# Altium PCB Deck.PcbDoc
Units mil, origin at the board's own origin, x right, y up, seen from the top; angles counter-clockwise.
Board outline 1157.48 x 1190.94 mil, 2 copper layers (Top Layer, Bottom Layer), stack 5.63 mil thick; 39 components, 27 nets, 140 pads, 61 vias.
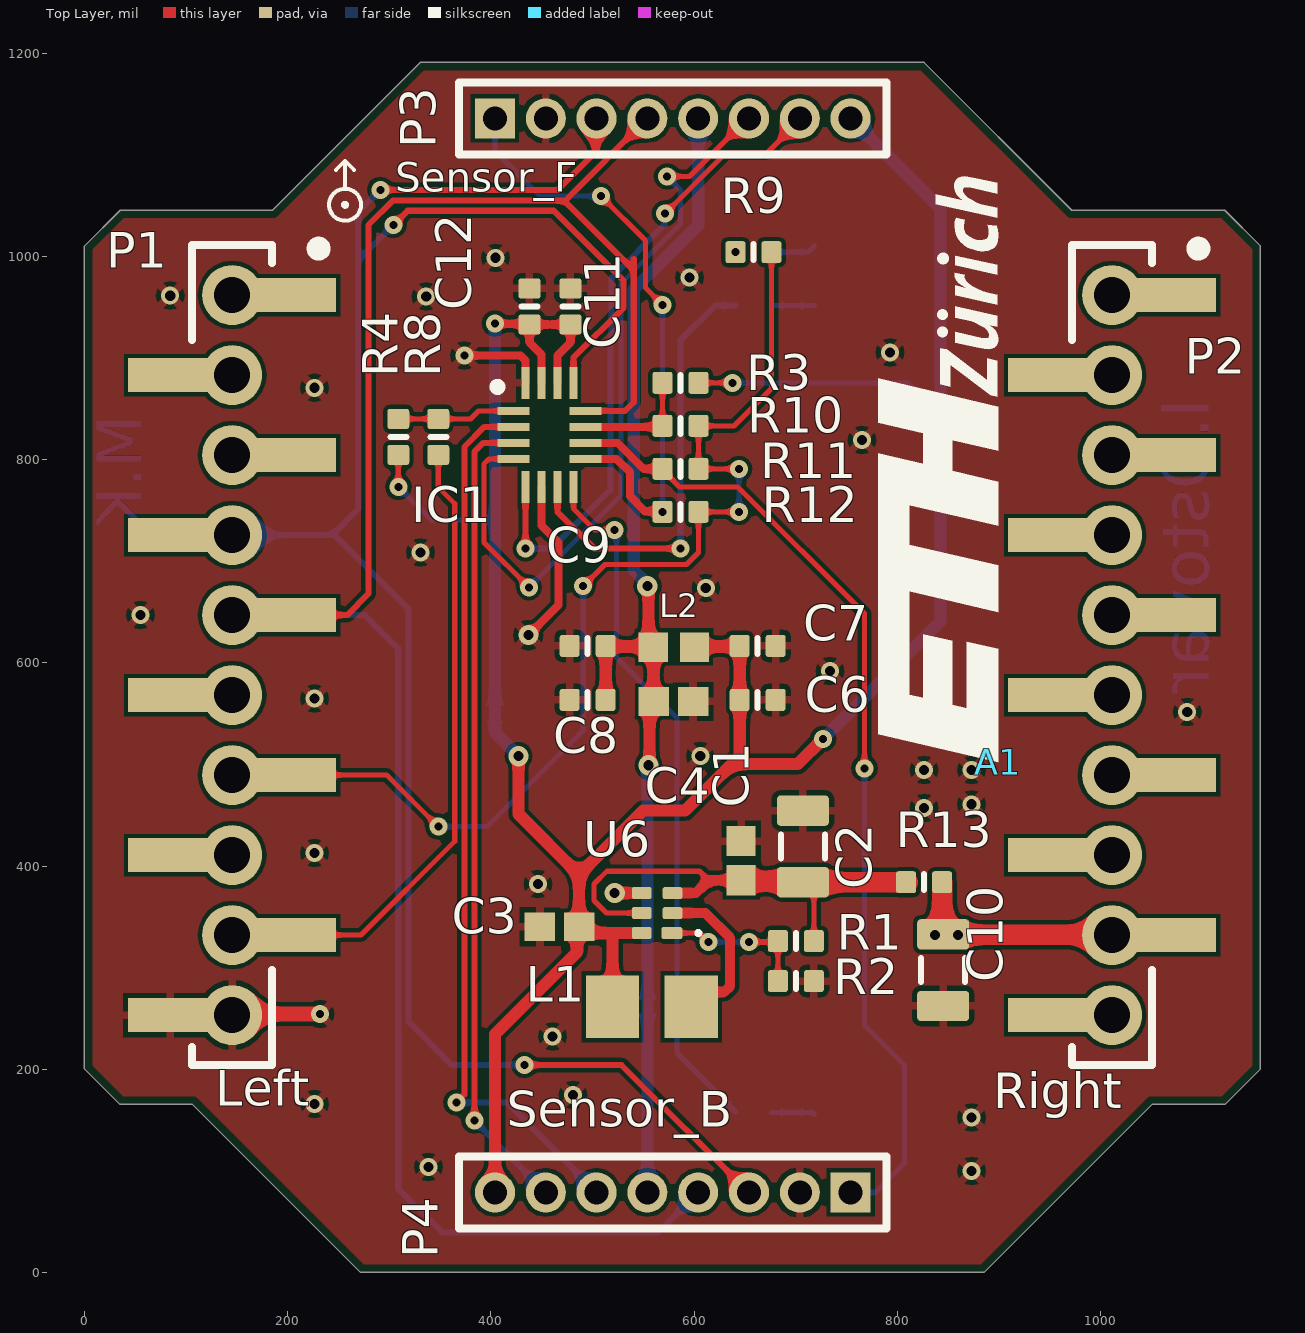
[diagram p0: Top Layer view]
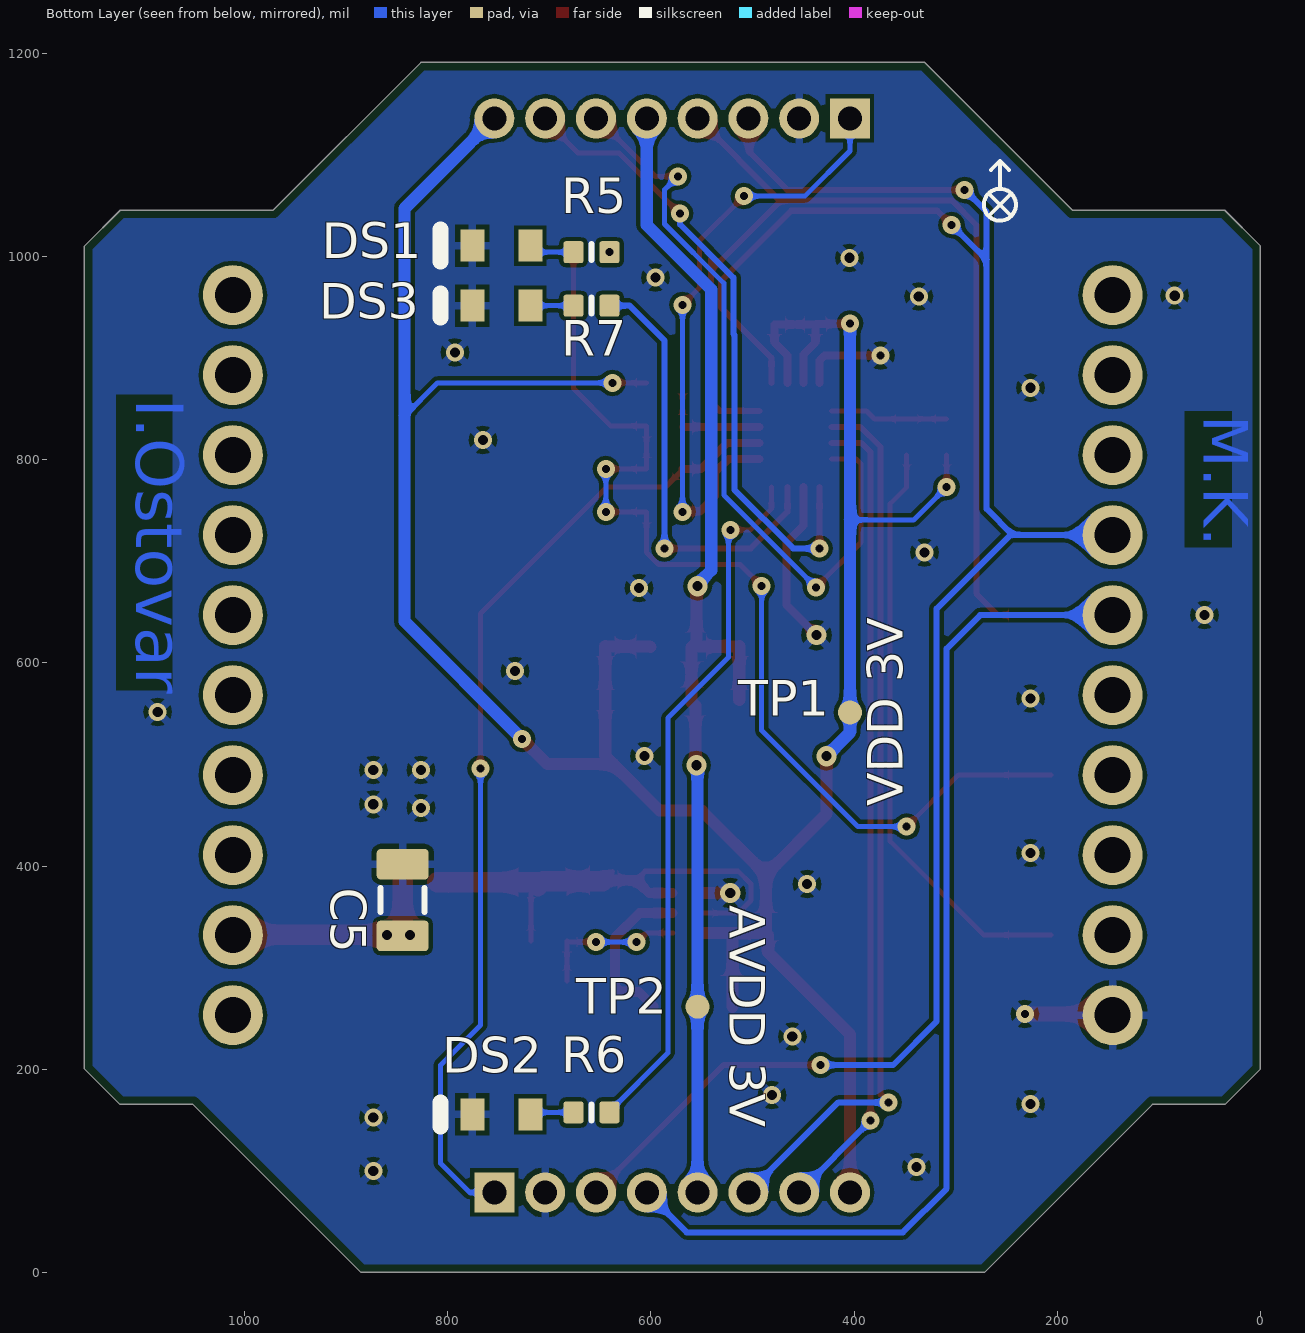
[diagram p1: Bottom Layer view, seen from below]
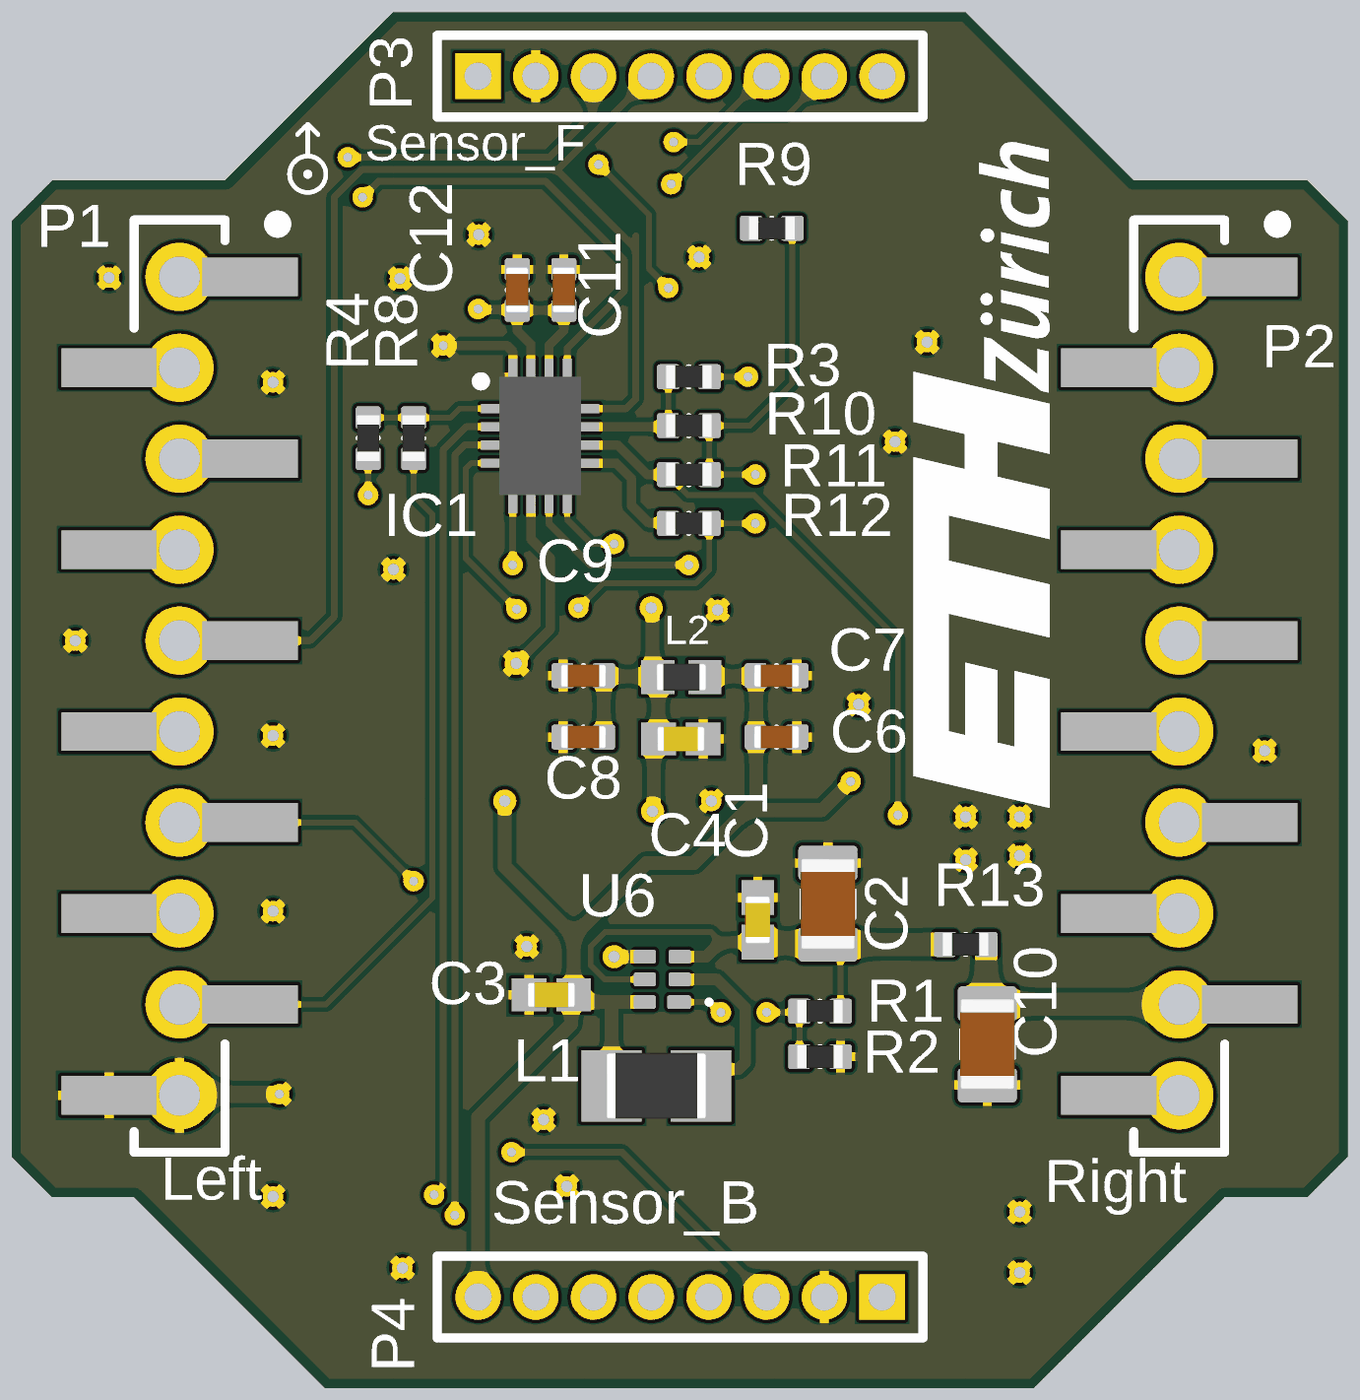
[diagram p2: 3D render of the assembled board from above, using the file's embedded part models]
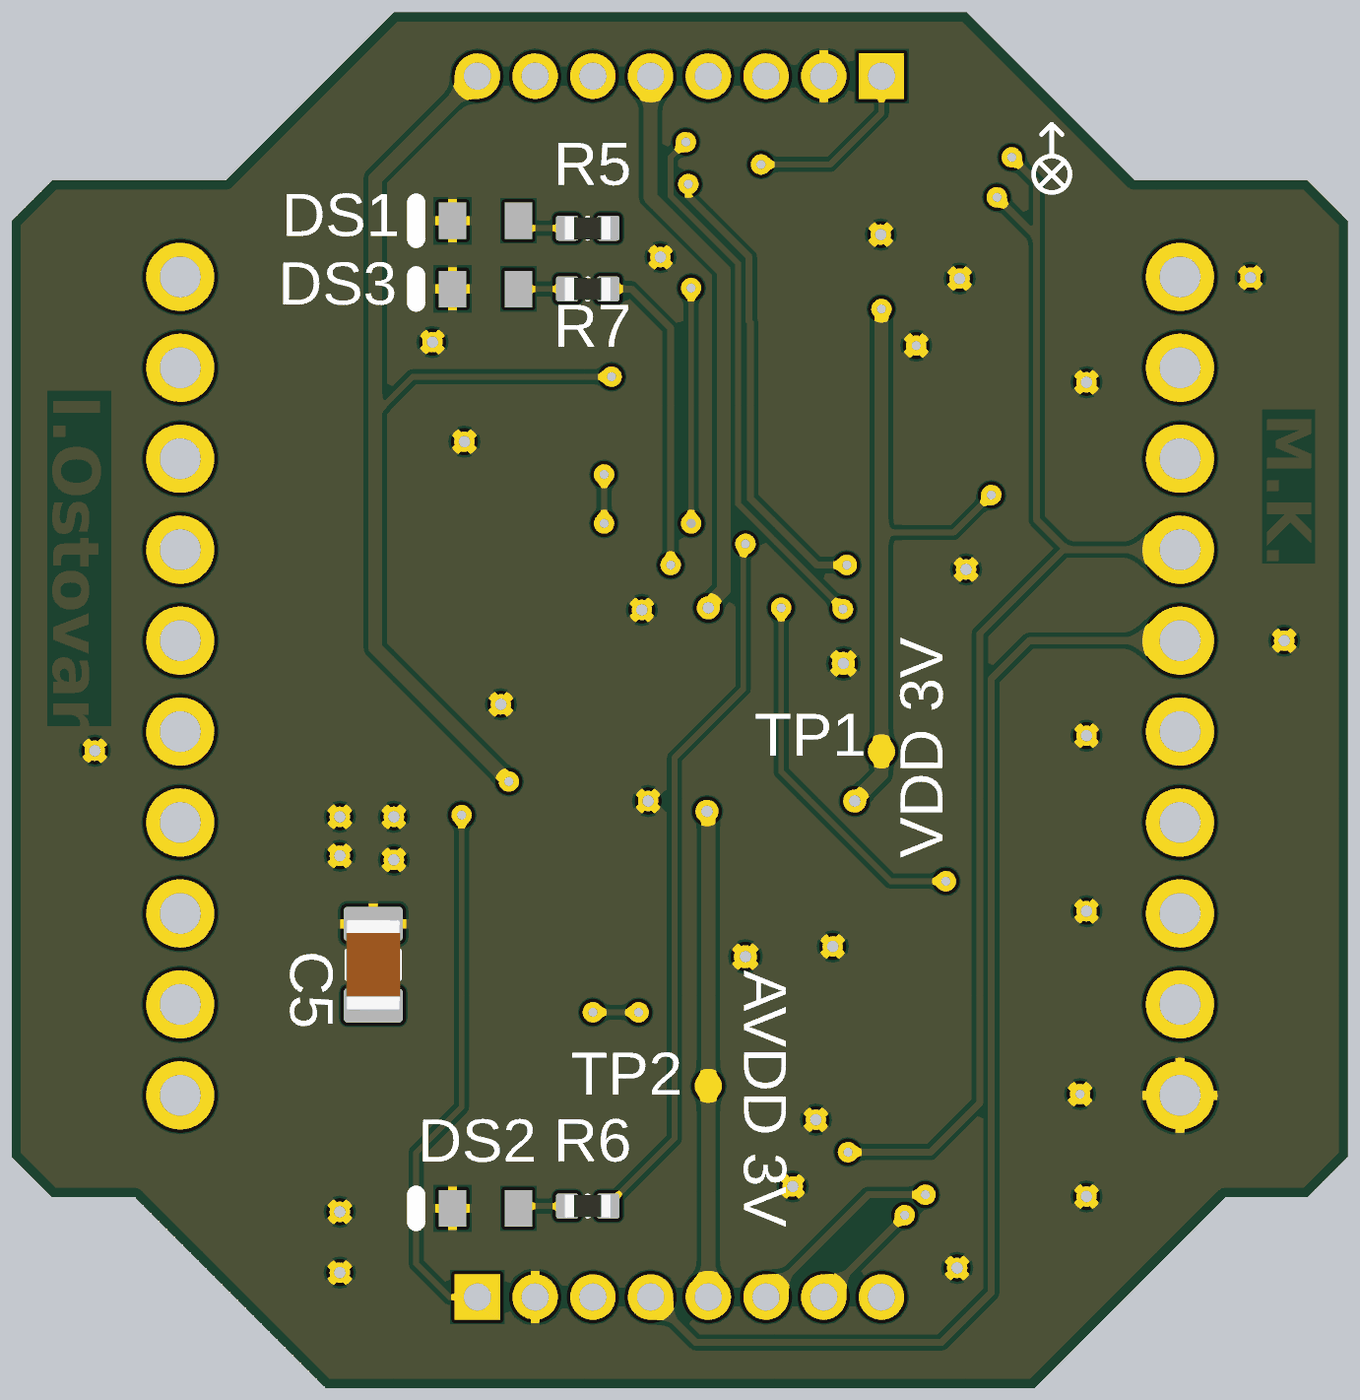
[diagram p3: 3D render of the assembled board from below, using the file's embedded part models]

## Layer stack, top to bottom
Top Solder: solder mask 0.3937, Solder Resist, Dk 3.5
Top Layer: signal copper 1.4173
Dielectric 1: prepreg 2.7953, FR-4, Dk 4.1
Bottom Layer: signal copper 1.4173
Bottom Solder: solder mask 0.3937, Solder Resist, Dk 3.5

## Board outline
35,165.35 106.3,165.35 271.65,0 885.45,0 1050.8,165.35 1122.48,165.35 1157.48,200.35 1157.48,1010.28 1122.24,1045.51 971.82,1045.51 826.39,1190.94 330.47,1190.94 185.04,1045.51 35.24,1045.51 0,1010.28 0,200.35

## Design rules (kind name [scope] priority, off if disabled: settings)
AcuteAngle [All] p1: minimum=6.00000000000000E+0001 checktracksonly=TRUE
BoardOutlineClearance switch [InComponent('SW1')] p1: gap=7.87 ignorepadtopadclearanceinfootprint=FALSE except(23.62: Track-OutlineEdge Track-CavityEdge Track-CutoutEdge Track-SplitBarrior Track-SplitContinuation)
BoardOutlineClearance [All] p2: gap=7.87 ignorepadtopadclearanceinfootprint=FALSE
Clearance Clearance_bga [TouchesRoom('VSOCBKP_BGA') or TouchesRoom('VCLUST_BGA')                  or TouchesRoom('uC_BGA')] p1: gap=2.95 ignorepadtopadclearanceinfootprint=FALSE except(0: Arc-Hole Track-Hole SMDPad-Hole THPad-Hole Via-Hole Fill-Hole Poly-Hole Region-Hole Text-Hole)
Clearance Clearance_pulp [All] p2: gap=3.94 ignorepadtopadclearanceinfootprint=FALSE except(0: Arc-Hole Track-Hole SMDPad-Hole THPad-Hole Via-Hole Fill-Hole Poly-Hole Region-Hole Text-Hole)
Clearance [All] p3: gap=4.92 ignorepadtopadclearanceinfootprint=FALSE except(0: Arc-Hole Track-Hole SMDPad-Hole THPad-Hole Via-Hole Fill-Hole Poly-Hole Region-Hole Text-Hole)
ComponentClearance ComponentClearance_moreweirdtphole [InComponent('TP27') vs InComponent('U2')] p1: gap=0 collisioncheckmode=3 verticalgap=0 showdistances=FALSE
ComponentClearance ComponentClearance_weird_tp_holes [InComponent('TP25') vs InComponent('TP26')] p2: gap=0 collisioncheckmode=3 verticalgap=0 showdistances=FALSE
ComponentClearance ComponentClearance_TPunderlatch [InComponent('U2') vs InComponent('TP23') or InComponent('JP21') or InComponent('JP27') or InComponent('JP24') or InComponent('JP25') or InComponent('JP26')] p3: gap=0 collisioncheckmode=3 verticalgap=0 showdistances=FALSE
ComponentClearance ComponentClearance_NetTie [InComponentClass('NetTie')] p4: gap=0 collisioncheckmode=3 verticalgap=0 showdistances=TRUE
ComponentClearance ComponentClearance_Hole [InComponentClass('Holes, Screws etc.')] p5: gap=0 collisioncheckmode=3 verticalgap=0 showdistances=TRUE
ComponentClearance [All] p6: gap=6 collisioncheckmode=3 verticalgap=6 showdistances=TRUE
DiffPairsRouting [All] p1: maxlimit=15 minlimit=4.92 mostfreqgap=4.92 toplayer_minwidth=4.92 toplayer_maxwidth=15 toplayer_prefwidth=11.81 bottomlayer_minwidth=4.92 bottomlayer_maxwidth=15 bottomlayer_prefwidth=11.81 maxuncoupledlength=500
FabricationTestpoint [All] p1: side=3 testpointundercomponent=TRUE minsize=19.68 maxsize=100 preferedsize=60 minholesize=0 maxholesize=40 preferedholesize=32 testpointgrid=1 allowsidetop=TRUE allowsidebottom=TRUE usegrid=TRUE gridtolerance=0.01
FanoutControl Fanout_BGA_1 [InComponent('U1')] p1: bgadir=Out bgaviamode=Centered fanoutstyle=BGA fanoutdirection=Alternating viagrid=1 // Fanout_BGA (Default Rule)
FanoutControl Fanout_BGA [IsBGA] p2: bgadir=Out bgaviamode=Centered fanoutstyle=Auto fanoutdirection=Alternating viagrid=1 // Fanout_BGA (Default Rule)
FanoutControl Fanout_LCC [IsLCC] p3: bgadir=Out bgaviamode=Centered fanoutstyle=Auto fanoutdirection=Alternating viagrid=1 // Fanout_LCC (Default Rule)
FanoutControl Fanout_SOIC [IsSOIC] p4: bgadir=Out bgaviamode=Centered fanoutstyle=Auto fanoutdirection=Alternating viagrid=1 // Fanout_SOIC (Default Rule)
FanoutControl Fanout_Small [(CompPinCount < 5)] p5: bgadir=Out bgaviamode=Centered fanoutstyle=Auto fanoutdirection=OutThenIn viagrid=1 // Fanout_Small (Default Rule)
FanoutControl Fanout_Default [All] p6: bgadir=Out bgaviamode=Centered fanoutstyle=Auto fanoutdirection=Alternating viagrid=1 // Fanout_Default (Default Rule)
Height [All] p1: minheight=0 maxheight=1968.5 prefheight=500
HoleSize [All] p1: absolutevalues=TRUE maxlimit=196.85 minlimit=7.87 maxpercent=80.000 minpercent=20.000
HoleToHoleClearance [All] p1: gap=9.84 allowstackedmicrovias=FALSE
Length "InNet('CLK_0') Or InNet('CLK_1')" [InNet('CLK_0') Or InNet('CLK_1')] p1: maxlimit=1447.75 minlimit=0
MinimumAnnularRing MinimumAnnularRing_Vias_bga [Isvia and TouchesRoom('GAP')] p1: minimumring=3.94
MinimumAnnularRing MinimumAnnularRing_Vias [Isvia] p2: minimumring=4.88
MinimumAnnularRing [All] p3: minimumring=5.91
MinimumSolderMaskSliver MinimumSolderMaskSliver_1 [InComponent('U2') and IsPad and InNet('GND')] p1: minsoldermaskwidth=0
MinimumSolderMaskSliver [All] p2: minsoldermaskwidth=3.93
PlaneClearance "Mounting Holes" [InPadClass('ExtendedClearance')] p1: clearance=82.68
PlaneClearance [All] p2: clearance=7.87
PlaneConnect [All] p1: planeconnectstyle=Direct reliefexpansion=20 reliefentries=4 reliefconductorwidth=10 reliefairgap=10
PolygonConnect [All] p1: thpad.connectstyle=Relief thpad.reliefconductorwidth=7.87 thpad.reliefentries=4 thpad.polygonreliefangle="90 Angle" thpad.airgapwidth=4.92 smdpad.connectstyle=Relief smdpad.reliefconductorwidth=7.87 smdpad.reliefentries=4 smdpad.polygonreliefangle="90 Angle" smdpad.airgapwidth=4.92 via.connectstyle=Relief via.reliefconductorwidth=7.87 via.reliefentries=4 via.polygonreliefangle="45 Angle" via.airgapwidth=4.92
RoomDefinition Deck [InComponentClass('Deck')] p1: confinementstyle=ConfineIn formatcopy=TRUE lockcomponents=FALSE outline -3696.85,-5580.71 -1696.85,-5580.71 -1696.85,-4580.71 -3696.85,-4580.71
RoutingVias RoutingVias_BGA [TouchesRoom('GAP')] p1: holewidth=7.87 width=15.75 viastyle="Through Hole" minholewidth=7.87 minwidth=15.75 maxholewidth=11.81 maxwidth=23.62 viatemplateguid#1={47C5AC95-9C33-4135-A81B-A9012375E807} viatemplatename#1=v40h15x30m0mx0
RoutingVias [All] p2: holewidth=7.87 width=17.72 viastyle="Through Hole" minholewidth=7.87 minwidth=17.72 maxholewidth=11.81 maxwidth=23.62
ShortCircuit ShortCircuit_variant_footprint [IsPad and not InAnyNet vs IsPad and not InAnyNet] p1: allowed=TRUE
ShortCircuit [All] p2: allowed=FALSE
SilkToSilkClearance "SilkText Exception" [OnSilkscreen  And (IsText And Not IsDesignator) vs OnSilkscreen  And ((IsText And Not IsDesignator) or IsTrack)] p1: silktosilkclearance=0
SilkToSilkClearance [All] p2: silktosilkclearance=3.94
SilkToSolderMaskClearance [IsPad] p1: minsilkscreentomaskgap=3.94 clearancetoexposedcopper=TRUE
SolderMaskExpansion [All] p1: expansion=2.95 istentingtop=FALSE
Width Width_bga [All] p1: maxlimit=23.62 minlimit=3.94 preferedwidth=4.92 minimp=50.000000 maximp=50.000000 favimp=50.000000
Width Width_PWR [InNetClass('POWER')] p2: maxlimit=23.62 minlimit=5.91 preferedwidth=7.87 minimp=50.000000 maximp=50.000000 favimp=50.000000
Width [All] p3: maxlimit=23.62 minlimit=5.91 preferedwidth=5.91 minimp=50.000000 maximp=50.000000 favimp=50.000000
13 further rules are at their usual default settings.

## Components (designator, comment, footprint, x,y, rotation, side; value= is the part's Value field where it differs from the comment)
A1 "Logo ETH Zurich" eth-zurich_3mm 899.23,502.06 r90 top
C1 "Capacitor 1 uF +/- 10% 6.3 V 1005" CAPC1005X55X25ML5T10 646.29,405.34 r270 top value=4.7µF
C2 "Capacitor 100µF +/-20% 6.3V 0805" CAPC0805(2012)145_L 707.12,419.12 r270 top value=100µF
C3 "Capacitor 1 uF +/- 10% 6.3 V 1005" CAPC1005X55X25ML5T10 467.52,340.36 r0 top value=4.7µF
C4 "Capacitor 1 uF +/- 10% 6.3 V 1005" CAPC1005X55X25ML5T10 579.72,562.01 r180 top value=4.7µF
C5 "Capacitor 100µF +/-20% 6.3V 0805" CAPC0805(2012)145_L 844.27,366.36 r270 bottom value=100µF
C6 "Capacitor 100nF +/-20% 25V 0402" CAPC0402(1005)60_L 662.6,563.58 r180 top value=1nF
C7 "Capacitor 100nF +/-20% 25V 0402" CAPC0402(1005)60_L 662.6,616.73 r180 top value=100nF
C8 "Capacitor 100nF +/-20% 25V 0402" CAPC0402(1005)60_L 495.28,563.58 r0 top value=10nF
C9 "Capacitor 100nF +/-20% 25V 0402" CAPC0402(1005)60_L 495.28,616.73 r0 top value=100nF
C10 "Capacitor 100µF +/-20% 6.3V 0805" CAPC0805(2012)145_L 845.19,297.72 r90 top value=100µF
C11 "Capacitor 100nF +/-20% 25V 0402" CAPC0402(1005)60_L 478.35,950.79 r270 top value=100nF
C12 "Capacitor 100nF +/-20% 25V 0402" CAPC0402(1005)60_L 437.99,950.79 r270 top value=100nF
DS1 "TLMS1100-GS08" VISH-TLMX1100_V 747.03,1010.63 r0 bottom
DS2 "TLMY1100-GS08" VISH-TLMX1100-2_V 747.03,155.51 r0 bottom
DS3 "TLMB1100-GS08" VISH-TLMX1100-2_V 747.03,951.57 r0 bottom
IC1 "TCA6408ARSVR" QFN40P180X260X55-16N 457.68,824.36 r0 top
L1 "1.0uH 1A" INDC2013X105X50ML20T20 558.46,261.62 r180 top
L2 "LQP15MN3N6B02D" MURA-LQP15MN3N6B02D-2_M 580.12,615.55 r180 top value=ferrit(5-15ohm)
P1 "Left" PCBComponent_1 141.57,555.28 r0 top locked
P2 "Right" PCBComponent_1 1007.57,555.28 r0 top locked
P3 "Sensor_F" MHDR1X8 404.02,1135.83 r0 top locked
P4 "Sensor_B" MHDR1X8 754.02,78.74 r180 top locked
R1 "Resistor 47K5 +/-1 % 0402 63 mW" RESC0402(1005)_L 700.23,326.21 r180 top value=47k
R2 "Jumper 0402" RESC0402(1005)_L 700.23,286.84 r180 top value=0
R3 "Resistor 47K5 +/-1 % 0402 63 mW" RESC0402(1005)_L 586.61,875.55 r0 top value=47k
R4 "Resistor 47K5 +/-1 % 0402 63 mW" RESC0402(1005)_L 308.86,822.4 r270 top value=47k
R5 "Resistor 47K5 +/-1 % 0402 63 mW" RESC0402(1005)_L 658.44,1004.23 r180 bottom value=3k3
R6 "Resistor 47K5 +/-1 % 0402 63 mW" RESC0402(1005)_L 658.44,157.52 r180 bottom value=3k3
R7 "Resistor 47K5 +/-1 % 0402 63 mW" RESC0402(1005)_L 658.44,951.57 r180 bottom value=3k3
R8 "Jumper 0402" RESC0402(1005)_L 348.23,822.4 r270 top value=0
R9 "Jumper 0402" RESC0402(1005)_L 658.44,1004.23 r0 top value=0
R10 "Jumper 0402" RESC0402(1005)_L 586.61,833.22 r180 top value=0
R11 "Jumper 0402" RESC0402(1005)_L 586.61,790.9 r180 top value=0
R12 "Jumper 0402" RESC0402(1005)_L 586.61,748.58 r180 top value=0
R13 "Jumper 0402" RESC0402(1005)_L 826.39,384.08 r0 top value=0
TP1 "VDD 3V" TP06R 404.02,551.18 r90 bottom
TP2 "AVDD 3V" TP06R 554.02,261.62 r90 bottom
U6 "TPS62233DRYR" DRY0006A 563.61,353.77 r180 top

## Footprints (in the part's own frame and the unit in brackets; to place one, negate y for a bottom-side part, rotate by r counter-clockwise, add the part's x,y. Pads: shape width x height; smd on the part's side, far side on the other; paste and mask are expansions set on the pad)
CAPC0402(1005)60_L [mm] "Chip Capacitor, Body 1.0x0.5mm, Height 0.6mm, IPC High Density"
  rrect25% 0.5x0.55 smd: 1(-0.45,0) 2(0.45,0)
  silkscreen extent 0,-0.2 0,0.2, body extent -0.5,-0.25 0.5,0.25, height 0.6
CAPC0805(2012)145_L [mm] "Chip Capacitor, Body 2.0x1.2mm, Height 1.45mm, IPC High Density"
  rrect25% 0.76x1.3 smd: 1(-0.9,0) 2(0.89,0)
  silkscreen extent -0.3,-0.55 0.3,0.55, body extent -1,-0.6 1,0.6, height 1.45
CAPC1005X55X25ML5T10 [mm] "Chip Capacitor, 2-Leads, Body 1.05x0.55mm, IPC Low Density"
  rect 0.76x0.72 smd: 1(-0.49,0) 2(0.49,0)
  body extent -0.53,-0.28 0.53,0.28, height 0.55
DRY0006A [mm] "SON, 6-Leads, Body 1.45x1mm, Pitch 0.5mm"
  rrect33% 0.52x0.3 smd: 1(-0.37,0.5)
  rrect33% 0.49x0.3 smd: 2(-0.385,0) 3(-0.385,-0.5) 4(0.385,-0.5) 5(0.385,0) 6(0.385,0.5)
  silkscreen extent -1.08,0.45 -0.98,0.55, body extent -0.5,-0.72 0.5,0.72, height 0.6
eth-zurich_3mm [mil]
  silkscreen extent 0,0 577,118
INDC2013X105X50ML20T20 [mm] "Chip Inductor, 2-Leads, Body 2.2x1.45mm, IPC Low Density"
  rect 1.33x1.57 smd: 1(-0.985,0) 2(0.985,0)
  body extent -1.1,-0.72 1.1,0.72, height 1.05
MHDR1X8 [mm] "Connector; Header; 8 Position"
  rect 1x1 hole 0.6: 1(0,0)
  round 1 hole 0.6: 2(1.27,0) 3(2.54,0) 4(3.81,0) 5(5.08,0) 6(6.35,0) 7(7.62,0) 8(8.89,0)
  silkscreen extent -0.9,-0.9 9.79,0.9
MURA-LQP15MN3N6B02D-2_M [mm] "Chip Inductor, 2-Leads, Body 1.10x0.60mm, IPC Low Density"
  rect 0.73x0.74 smd: 1(-0.515,0) 2(0.515,0)
  body extent -0.55,-0.3 0.55,0.3, height 0.45
PCBComponent_1 [mm]
  round 1.5 hole 0.9: 1(0.098,10.332) 2(0.098,8.332) 3(0.098,6.332) 4(0.098,4.332) 5(0.098,2.332) 6(0.098,0.332) 7(0.098,-1.668) 8(0.098,-3.668) 9(0.098,-5.668) 10(0.098,-7.668)
  rect 2.1x0.85 smd: 1(1.648,10.332) 2(-1.452,8.332) 3(1.648,6.332) 4(-1.452,4.332) 5(1.648,2.332) 6(-1.452,0.332) 7(1.648,-1.668) 8(-1.452,-3.668) 9(1.648,-5.668) 10(-1.452,-7.668)
  silkscreen extent -0.9,-8.92 2.41,11.64, body extent -0.9,-8.92 1.1,11.58, height 3
QFN40P180X260X55-16N [mm]
  rect 0.8x0.2 smd: 1(-0.9,0.6) 2(-0.9,0.2) 3(-0.9,-0.2) 4(-0.9,-0.6) 9(0.9,-0.6) 10(0.9,-0.2) 11(0.9,0.2) 12(0.9,0.6)
  rect 0.2x0.8 smd: 5(-0.6,-1.3) 6(-0.2,-1.3) 7(0.2,-1.3) 8(0.6,-1.3) 13(0.6,1.3) 14(0.2,1.3) 15(-0.2,1.3) 16(-0.6,1.3)
  silkscreen extent -1.4,1.1 -1.2,1.3, body extent -0.9,-1.3 0.9,1.3, height 0.55
RESC0402(1005)_L [mm] "Chip Resistor, Body 1.0x0.5mm, IPC High Density"
  rrect25% 0.5x0.55 smd: 1(-0.45,0) 2(0.45,0)
  silkscreen extent 0,-0.2 0,0.2, body extent -0.5,-0.25 0.5,0.25, height 0.3
TP06R [mm] "Testpoint, round, d=0.6mm"
  round 0.6 smd paste-1: 1(0,0)
VISH-TLMX1100-2_V [mm] "SMD, 2-Leads, Body 1.6x0.8mm"
  rect 0.6x0.8 smd: 1(-0.725,0) 2(0.725,0)
  silkscreen extent 1.53,-0.3 1.53,0.3, body extent -0.8,-0.4 0.8,0.4, height 0.65
VISH-TLMX1100_V [mm] "SMD, 2-Leads, Body 1.6x0.8mm"
  rect 0.6x0.8 smd: 1(-0.725,0) 2(0.725,0)
  silkscreen extent 1.53,-0.4 1.53,0.4, body extent -0.8,-0.4 0.8,0.4, height 0.65

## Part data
A1: library part CMP-00038-1
C1 C3 C4: library part CMP-001-00009-6, "Chip Capacitor, 1 uF, +/- 10%, 6.3 V, 1005 (0402 Metric)", Capacitor Type=Ceramic, Case/Package=0402, Max Operating Temperature=85°C, Min Operating Temperature=-55°C, Tolerance=10%, Voltage Rating=6.3V
C2 C5 C10: library part CMP-001-00054-4, "Chip Capacitor, 100µF +/-20%, 6.3V, 0805, Thickness 1.45 mm", Case/Package=0805, Max Operating Temperature=85°C, Min Operating Temperature=-55°C, Tolerance=10%, Voltage Rating=6.3V
C6 C7 C8 C9 C11 C12: library part CMP-001-00065-4, "Chip Capacitor, 100nF +/-20%, 25V, 0402, Thickness 0.6 mm", Case/Package=0402, Max Operating Temperature=85°C, Min Operating Temperature=-55°C, Tolerance=10%, Voltage Rating=25V
DS1: library part CMP-007-00030-2, "Red Led, 20mA, 2.1 V, -40 to 100 degC, 2-Pin SMD (0603), RoHS, Tape and Reel", Case/Package=0603, Colour=Red, Forward Current=20mA, Forward Voltage=2.1V, Manufacturer="Vishay Semiconductor", Max Operating Temperature=100°C, Min Operating Temperature=-40°C, Package Description="2-Pin Surface Mount Device, Body 1.6 x 0.8 mm", Package Quantity=3000, Package Reference=TLMX1100, Power=90mW
DS2: library part CMP-007-00031-2, "Yellow LED, 20 mA, 2.1 V, -40 to 100 degC, 2-Pin SMD (0603), RoHS, Tape and Reel", Case/Package=0603, Colour=Yellow, Forward Current=20mA, Forward Voltage=2.1V, Manufacturer="Vishay Semiconductor", Max Operating Temperature=100°C, Min Operating Temperature=-40°C, Package Description="2-Pin Surface Mount Device, Body 1.6 x 0.8 mm", Package Quantity=3000, Power=90mW
DS3: library part CMP-007-00028-2, "Blue LED, 10 mA, 3.9 V, -40 to 100 degC, 2-Pin SMD (0603), RoHS, Tape and Reel", Case/Package=0603, Colour=Blue, Forward Current=10mA, Forward Voltage=3.9V, Manufacturer="Vishay Semiconductor", Max Operating Temperature=100°C, Min Operating Temperature=-40°C, Package Description="2-Pin Surface Mount Device, Body 1.6 x 0.8 mm", Package Quantity=3000, Power=68mW
IC1: "Integrated Circuit", Manufacturer_Name="Texas Instruments", Mouser Part Number=595-TCA6408ARSVR
L1: library part CMP-006-00000-3, "1.0uH 1150mA", Case/Package=0805, Current Rating=1.5A, Manufacturer=Murata, Max Operating Temperature=125°C, Min Operating Temperature=-55°C, Package Description="2-Pin Surface Mount Device, Body 2 x1.25 mm", Package Quantity=4000, Resistance=90mohm, Tolerance=25%
L2: library part CMP-006-00010-6, "Inductor, 500 MHz, 500 mA, 5 Ohm, -40 to 85 degC, 01005 (0402 Metric),", Case/Package=0402, Current Rating=170mA, Manufacturer=Murata, Max Operating Temperature=85°C, Min Operating Temperature=-40°C, Package Description="2-Pin Surface Mount Device, Body 1 x 0.5 mm", Package Quantity=10000, Self Resonant Frequency=6GHz
P1 P2: library part MHDR1X10, "Header, 10-Pin"
P3 P4: library part MHDR1X8, "Header, 8-Pin"
R1 R3 R4 R5 R6 R7: library part CMP-009-00137-3, "Chip Resistor, 47,5 kOhms, +/-1 %, 63 mW, -55 to 155 degC, 0402", Case/Package=0402, Max Operating Temperature=155°C, Min Operating Temperature=-55°C, Power=63mW, Tolerance=1%
R2 R8 R9 R10 R11 R12: library part CMP-009-00148-3, Case/Package=0402, Max Operating Temperature=155°C, Min Operating Temperature=-55°C
R13: library part CMP-009-00148-3, "Current sensing jumper OR Fuse", Case/Package=0402, Max Operating Temperature=155°C, Min Operating Temperature=-55°C
TP1 TP2: library part CMP-00028-00002-2, "0.6mm round"
U6: library part CMP-0323-00281-3, "Buck Step Down Regulator with 2.05 to 6 V Input and 3 V Output, -40 to 85 degC, 6-Pin SON (DRY), Green (RoHS & no Sb/Br)", Manufacturer="Texas Instruments", Rating=Catalog, Switch Current Limit(Typ)(A)=0.84

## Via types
v1: diameter 17.72, hole 7.87, Top Layer to Bottom Layer, 28 vias
v2: diameter 17.72, hole 10, Top Layer to Bottom Layer, 26 vias
v3: diameter 20, hole 10, Top Layer to Bottom Layer, 7 vias

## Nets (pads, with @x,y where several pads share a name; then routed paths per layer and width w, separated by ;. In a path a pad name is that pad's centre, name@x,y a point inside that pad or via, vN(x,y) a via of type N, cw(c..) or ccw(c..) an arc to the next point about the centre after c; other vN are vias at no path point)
3V_in: P1.1
\INT_Exp: IC1.11 R3.1 R10.2 | length 118.5
  Top Layer w5: R10.2@567.98,832.3 R10.2 R3.1
  Top Layer w8: IC1.11 493.17,832.3 R10.2@567.98,832.3
\RESET: IC1.1 R4.1 R8.1 | length 116.6
  Top Layer w5: R4.1 R8.1 379.92,840.11 387.8,847.99 IC1.1
\RESET_u: P1.9 R8.2 | length 583.3
  Top Layer w5: P1.9@206.45,332.13 272.27,332.13 364.48,424.35 364.48,756.59 348.23,772.84 R8.2
AVDD: C4.2 C8.2 C9.2 L2.2 P3.5 P4.5 TP2.1 | length 1196.1
  Top Layer w6: P3.5@606.66,1134.24 P3.5@608.24,1135.83
  Top Layer w12: C8.2 C9.2 513.58,616.14 L2.2@559.25,616.14 ; v3(554.02,675.51) 555.12,674.42 555.12,620.28 L2.2@559.25,616.14 ; v3(555.12,499.29) 556.21,500.39 556.21,557.78 C4.2 560.14,562.3 560.14,615.26 L2.2 L2.2@559.25,616.14
  Bottom Layer w12: P4.5 TP2.1 554.02,498.2 v3(555.12,499.29) ; v3(554.02,675.51) 554.02,677.68 540.65,691.05 540.65,967.53 604.02,1030.91 P3.5
GND: C1.1 C2.1 C3.1 C4.1 C5.1 C6.1 C7.1 C8.1 C9.1 C10.1 C11.1 C12.1 DS1.2 DS2.2 DS3.2 IC1.6 IC1.16 P1.10 P3.2 P4.2 R2.1 U6.4 | length 367.9
  Top Layer w8: v1(373.92,902.56) 429.04,902.56 433.99,897.61 433.99,875.61 IC1.16 ; v3(437.02,627.36) 466.5,656.84 466.5,718.48 449.8,735.18 IC1.6
  Top Layer w12: v3(521.85,373.45) U6.4
  Top Layer w15: P1.10@146.45,254.41 v1(231.95,254.41)
  Top Layer w20: P1.10@145.43,253.39 P1.10@146.45,254.41 ; P4.2 P4.2@704.02,83.98
  other v2: 873.21,99.88 338.48,103.91 873.21,152.52 226.38,165.78 480.91,174.55 460.81,232.24 446.22,382.31 226.38,412.81 826.39,457.26 873.21,460.8 826.39,494.54 873.21,494.54 606.13,508.24 1085.4,551.79 226.38,564.79 733.69,591.93 55.12,647.09 611.56,673.69 330.72,708.72 765.27,819.35 226.38,870.78 792.93,905.58 336.33,960.62 84.41,961.42 595.52,979.18 404.6,998.66
I2C_RST_B: IC1.5 P3.7 | length 634.7
  Top Layer w5: v1(571.31,1042.34) 571.73,1042.34 631.28,1101.89 671.67,1101.89 704.02,1134.24 P3.7
  Top Layer w6: v1(434.05,712.6) IC1.5
  Bottom Layer w6: v1(434.05,712.6) 459.89,712.6 517.72,770.43 517.72,922.59 518.77,923.65 518.77,979.18 571.31,1031.72 v1(571.31,1042.34)
I2C_RST_F: IC1.3 P4.7 | length 800
  Top Layer w6: v1(383.86,149.65) 383.86,807.63 392.72,816.49 IC1.3
  Bottom Layer w6: v1(383.86,149.65) 383.86,149.28 454.02,79.11 P4.7
INT_Sens_B: IC1.9 P3.1 R12.2 | length 601.8
  Top Layer w5: v1(508.36,1059.37) 552.11,1015.63 552.11,969.23 v1(568.9,952.44)
  Top Layer w8: IC1.9 523.76,800.74 536.81,787.69 536.81,764.09 551.74,749.16 568.32,749.16 v1(568.9,748.58)
  Bottom Layer w5: P3.1 404.02,1103.82 448.47,1059.37 v1(508.36,1059.37) ; v1(568.9,748.58) v1(568.9,952.44)
INT_Sens_F: IC1.10 P4.1 R11.2 | length 967.1
  Top Layer w5: R11.2 568.9,789.92 585.63,773.18 643.11,773.18 767.72,648.58 v1(767.72,496.06)
  Top Layer w8: IC1.10 524.89,816.49 550.48,790.9 R11.2
  Bottom Layer w5: P4.1 778.38,78.74 807.07,107.43 807.07,204.07 767.72,243.42 v1(767.72,496.06)
IO_u: P1.7 R9.2 R10.1 R11.1 R12.1 | length 1039.7
  Top Layer w5: P1.7@206.45,489.61 297.42,489.61 v1(348.23,438.8) ; v1(490.91,675.51) 512.25,696.85 592.5,696.85 604.33,708.68 R12.1 v1(644.29,748.58) ; v1(644.29,790.9) R11.1 R10.1 639.4,833.22 676.16,869.98 R9.2
  Bottom Layer w5: v1(348.23,438.8) 396.2,438.8 490.91,533.51 v1(490.91,675.51) ; v1(644.29,748.58) v1(644.29,790.9)
LED1: R5.2 R9.1
  other v1: 640.73,1004.23
LED2: IC1.8 R6.2 | length 693.2
  Top Layer w5: IC1.8 481.3,751.73 502.17,730.86 v1(521.85,730.86)
  Bottom Layer w5: v1(521.85,730.86) 523.76,728.95 523.76,605.18 583.3,545.64 583.3,215.93 640.73,158.51 R6.2
LED3: IC1.7 R7.2 | length 433.6
  Top Layer w6: IC1.7 465.55,748.58 501.53,712.6 v1(586.61,712.6)
  Bottom Layer w6: v1(586.61,712.6) 586.61,917.35 620.84,951.57 R7.2
LPn_B: IC1.4 P3.6 | length 746.5
  Top Layer w5: IC1.4 398.14,800.74 393.3,795.9 393.3,718.54 v1(437.42,674.42) ; v1(573.46,1078.8) 595.55,1078.8 652.58,1135.83 P3.6
  Bottom Layer w5: v1(437.42,674.42) 528.21,765.21 528.21,973.62 586.61,1032.02 586.61,1065.64 v1(573.46,1078.8)
LPn_F: IC1.2 P4.6 | length 879.8
  Top Layer w6: v1(365.94,167.32) 366.01,167.32 373.92,175.24 373.92,812.46 393.7,832.24 IC1.2
  Bottom Layer w6: v1(365.94,167.32) 415.44,167.32 P4.6
NetC1_2: C1.2 C2.2 R1.1 R13.1 U6.3 U6.5 | length 501.8
  Top Layer w5: U6.5 513.76,353.77 501.53,365.99 501.53,382.29 514.12,394.88 605.53,394.88 614.37,386.05 ; C1.2@637.83,394.51 C1.2 ; C2.2@706.13,385.06 C2.2 ; C2.2@711.05,380.15 717.95,373.25 R1.1
  Top Layer w10: U6.3 601.77,373.45 614.37,386.05 C1.2
  Top Layer w20: C1.2 647.28,385.06 C2.2@706.13,385.06 ; C2.2 C2.2@714.97,384.08 ; C2.2@711.05,380.15 C2.2@714.97,384.08 ; R13.1@810.23,384.08 C2.2@714.97,384.08
NetDS1_1: DS1.1 R5.1 | length 45
  Bottom Layer w5: R5.1 712.09,1004.23 DS1.1
NetDS2_1: DS2.1 R6.1 | length 43.2
  Bottom Layer w5: R6.1 716.47,157.52 DS2.1
NetDS3_1: DS3.1 R7.1 | length 42.3
  Bottom Layer w5: R7.1 DS3.1
NetL1_1: L1.1 U6.2 | length 160.9
  Top Layer w10: U6.2 610.99,353.77 635.46,329.29 635.46,281.87 629.61,276.01 611.64,276.01 L1.1
NetR1_2: R1.2 R2.2 U6.1 | length 147.8
  Top Layer w5: U6.1 604.42,334.08 613.28,325.23 v1(614.37,325.23) ; v1(654.02,325.29) 681.59,325.29 R1.2 R2.2
  Bottom Layer w5: v1(614.37,325.23) 653.96,325.23 v1(654.02,325.29)
SCL: IC1.12 P1.5 P3.4 P4.4 | length 2089.4
  Top Layer w6: P1.5@206.45,647.09 258.45,647.09 279.53,668.17 279.53,1030.96 303.52,1054.95 472.25,1054.95 ; IC1.12 532.2,847.99 540.65,856.44 540.65,986.56 ; 540.65,997.5 540.65,986.56 ; P3.4 473.15,1054.95 472.25,1054.95 ; 472.25,1054.95 540.65,986.56
  Bottom Layer w6: P1.5@145.43,647.09 275.87,647.09 308.86,614.1 308.86,82.53 352.02,39.37 564.65,39.37 P4.4
SDA: IC1.13 P1.4 P3.3 P4.3 | length 2108.5
  Top Layer w6: v1(291.14,1065.57) 465.84,1065.57 502.17,1101.89 ; v1(304.02,1030.96) 318.07,1045.01 461.93,1045.01 530.71,976.24 530.71,949.7 481.3,900.29 IC1.13 ; v1(432.99,204.18) 528.58,204.18 P4.3 ; P3.3 P3.3@502.17,1133.97 ; 502.17,1101.89 504.02,1103.75 504.02,1132.11 P3.3@502.17,1133.97 ; 502.17,1101.89 P3.3@502.17,1133.97
  Bottom Layer w5: P3.3@508.24,1126.53 P3.3@508.24,1135.83
  Bottom Layer w6: P1.4@145.43,725.83 243.7,725.83 ; v1(291.14,1065.57) 269.59,1044.02 269.59,996.53 ; v1(304.02,1030.96) 269.59,996.53 ; v1(432.99,204.18) 361.67,204.18 318.8,247.05 318.8,653.27 246.23,725.83 243.7,725.83 ; 243.7,725.83 269.59,751.73 269.59,996.53
VCOM: C5.2 C10.2 P2.9 R13.2 | length 230.2
  Top Layer w20: R13.2 844.24,383.94 844.24,337.72 838.65,332.13 v3(837.22,332.13) v3(859.86,332.13) 860.17,332.45 1011.12,332.45 P2.9@1011.43,332.13
VDD: C3.2 C6.2 C7.2 C11.2 C12.2 IC1.14 IC1.15 L1.2 L2.1 P3.8 P4.8 R3.2 R4.2 TP1.1 U6.6 | length 2816.6
  Top Layer w5: v1(308.86,773.18) R4.2 ; R3.2 R3.2 v1(637.83,875.61)
  Top Layer w8: v1(404.02,934.22) 404.6,933.65 437.42,933.65 C12.2 ; IC1.15 449.74,875.61 449.74,903.61 437.99,915.35 C12.2 ; IC1.14 465.55,902.56 478.35,915.35 C11.2 C12.2
  Top Layer w12: P4.8 404.02,234.54 484.7,315.22 484.7,332.19 486.69,334.18 C3.2@486.81,334.18 ; v3(427.17,508.24) 427.17,451.14 486.81,391.5 ; L1.2 519.68,331.62 517.13,334.18 ; U6.6 548.36,334.18 517.13,334.18 ; L2.1 600.98,616.14 644.29,616.14 C7.2 C6.2 644.88,508.24 637.02,500.39 ; v1(726.8,525.12) 702.06,500.39 637.02,500.39 ; C3.2@486.81,334.18 517.13,334.18 ; C3.2@486.81,334.18 C3.2 486.81,391.5 ; 486.81,391.5 549.87,454.55 591.19,454.55 637.02,500.39
  Bottom Layer w5: v1(308.86,773.18) 341.34,740.7 404.02,740.7 ; v1(637.83,875.61) 809.99,875.61 842.53,843.07 ; P3.8@752.58,1130.17 P3.8@758.24,1135.83 ; 841.09,875.61 842.53,874.17
  Bottom Layer w12: v1(404.02,934.22) 404.02,740.7 TP1.1 404.02,531.39 v3(427.17,508.24) ; v1(726.8,525.12) 842.53,640.85 842.53,843.07 842.53,874.17 842.53,1047.32 798.28,1091.57 756.13,1133.72 P3.8
VUSB: P2.10
pads on no net: P1.2 P1.3 P1.6 P1.8 P2.1 P2.2 P2.3 P2.4 P2.5 P2.6 P2.7 P2.8

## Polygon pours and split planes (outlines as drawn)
GND on Top Layer "GND_L01_P000" (solid, pour order 0): 0,1010.28 35.24,1045.51 185.04,1045.51 330.47,1190.94 826.39,1190.94 972.06,1045.28 1122,1045.28 1122.24,1045.51 1157.48,1010.28 1157.48,200.35 1122.48,165.35 1050.8,165.35 885.45,0 271.65,0 106.3,165.35 35,165.35 0,200.35
GND on Bottom Layer "GND_L02_P001" (solid, pour order 1): 0,1010.28 0,200.35 35,165.35 106.3,165.35 271.65,0 885.45,0 1050.8,165.35 1122.48,165.35 1157.48,200.35 1157.48,1009.8 1121.77,1045.51 971.82,1045.51 826.39,1190.94 330.47,1190.94 185.04,1045.51 35.24,1045.51

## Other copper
Bottom Layer:
  text "I.Ostovar" at 1121.59,859.8 h80 r90
  text "M.K." at 69.92,843.54 h75 r90

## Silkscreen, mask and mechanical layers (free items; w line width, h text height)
Top Overlay:
  circle w3.94: c256.48,1050.9 r15.75
  circle w3.94: c256.48,1050.9 r1.97
  lines w3.94: 247.62,1085.35 256.48,1094.2 ; 256.48,1066.64 256.48,1094.2 ; 265.34,1085.35 256.48,1094.2
Bottom Overlay:
  circle w3.94: c256.48,1050.9 r15.75
  lines w3.94: 245.66,1040.07 267.31,1061.72 ; 247.62,1085.35 256.48,1094.2 ; 256.48,1066.64 256.48,1094.2 ; 265.34,1085.35 256.48,1094.2 ; 267.31,1040.07 245.66,1061.72 ; 245.66,1061.72 245.66,1061.72
Mechanical 12:
  lines w5: 787.4,1190.94 790.35,1190.94 ; 971.82,1045.51 1122.24,1045.51 1157.48,1010.28 1157.48,200.35 1122.48,165.35 1050.8,165.35 ; 972.06,1045.28 826.39,1190.94 330.47,1190.94 185.04,1045.51 35.24,1045.51 0,1010.28 0,200.35 35,165.35 106.3,165.35 271.65,0 885.45,0 1050.8,165.35 ; 1050.8,165.35 1050.8,165.35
